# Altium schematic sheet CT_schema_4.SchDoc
size 396 x 205 mm
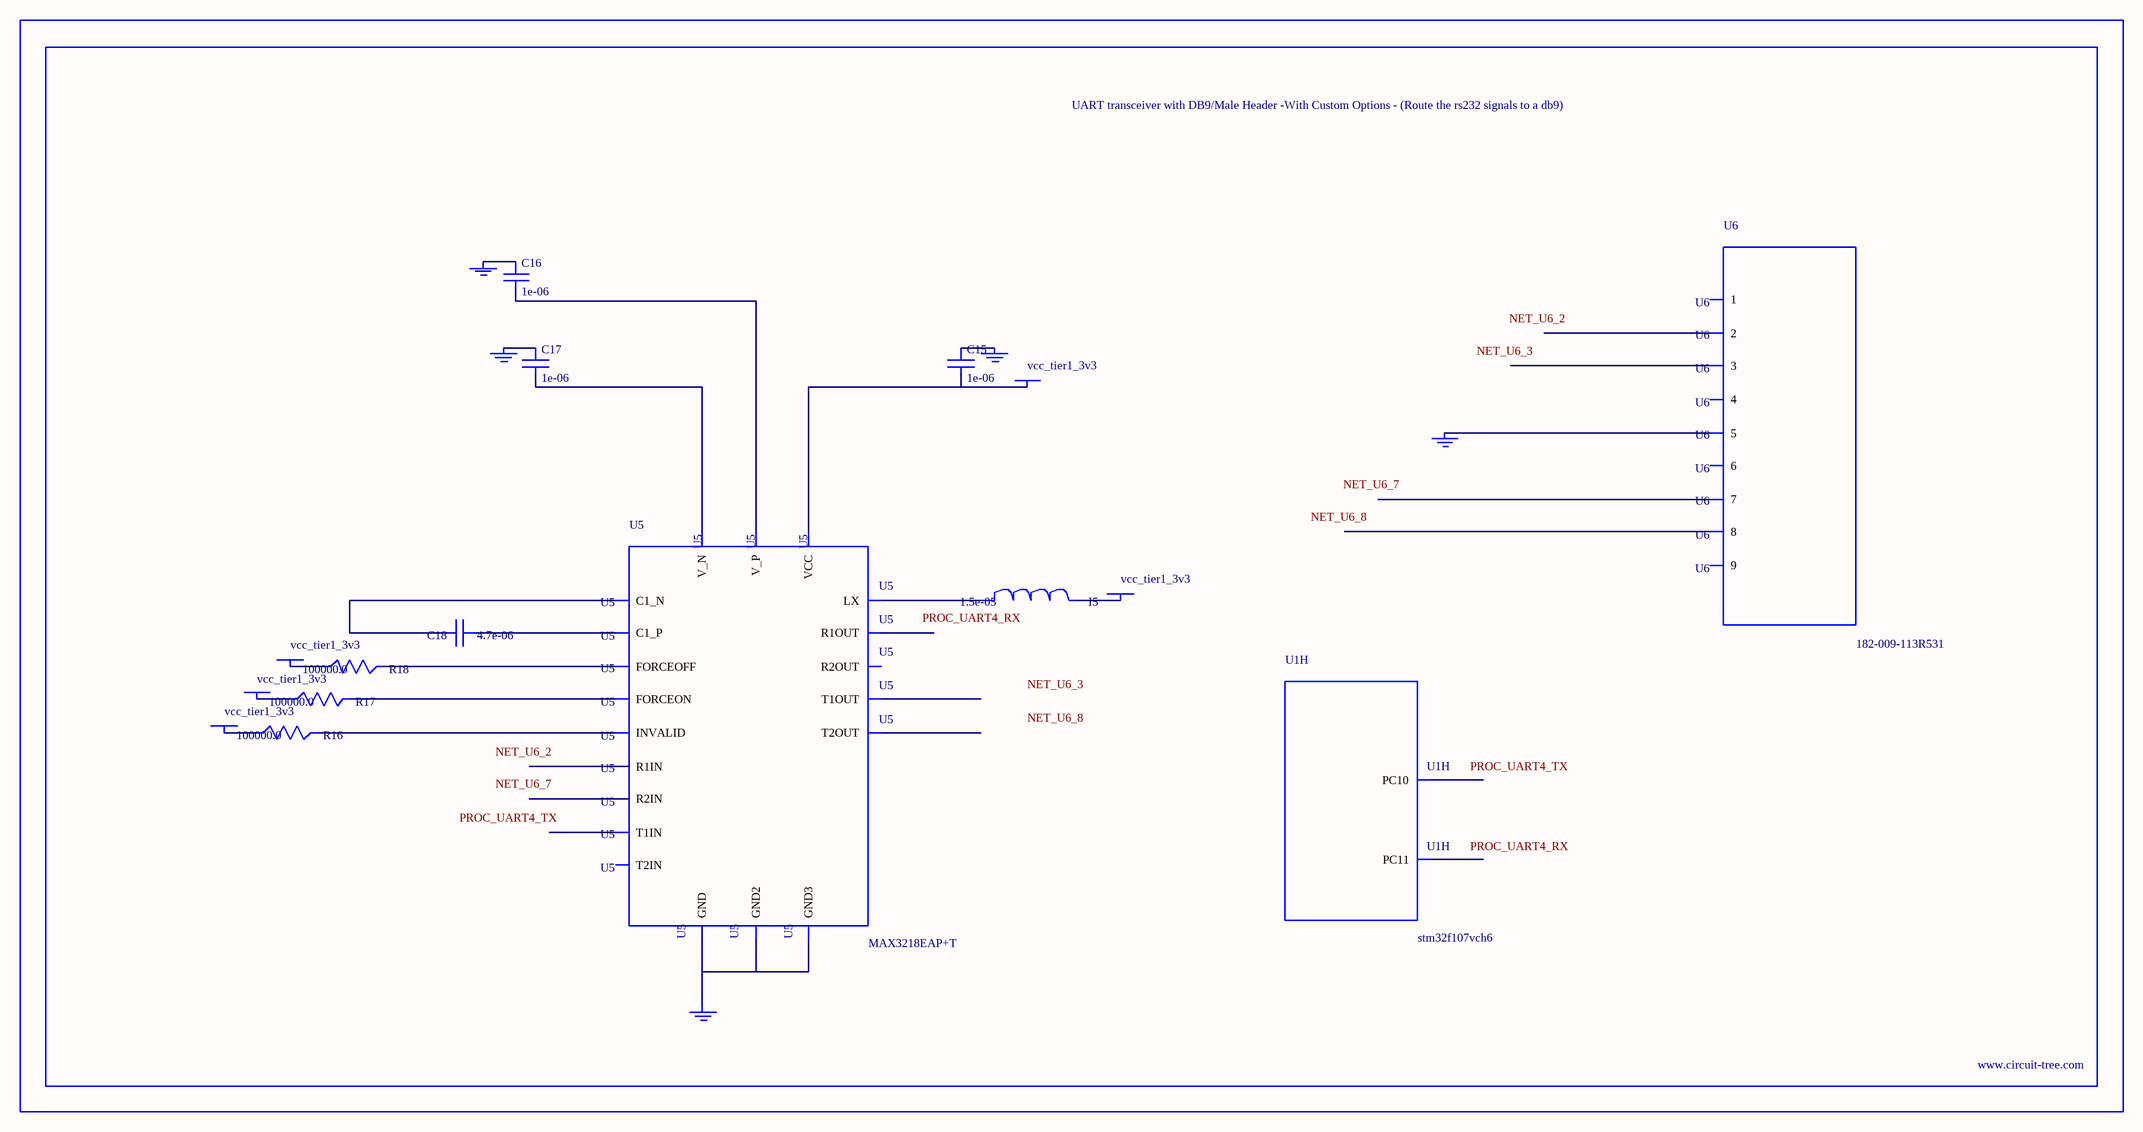
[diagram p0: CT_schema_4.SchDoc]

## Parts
BORDER3  (no value)
C15  1e-06  [C0603]
C16  1e-06  [C0603]
C17  1e-06  [C0603]
C18  4.7e-06  [C0805]
GND_INSTANCE_3_0  (no value)
GND_INSTANCE_3_1  (no value)
GND_INSTANCE_3_2  (no value)
GND_INSTANCE_3_3  (no value)
GND_INSTANCE_3_4  (no value)
I5  1.5e-05  [L1210]
POWER_INSTANCE_3_0  vcc_tier1_3v3
POWER_INSTANCE_3_1  vcc_tier1_3v3
POWER_INSTANCE_3_2  vcc_tier1_3v3
POWER_INSTANCE_3_3  vcc_tier1_3v3
POWER_INSTANCE_3_4  vcc_tier1_3v3
R16  100000.0  [R0603]
R17  100000.0  [R0603]
R18  100000.0  [R0603]
U1  stm32f107vch6  [LFBGA100]  (part H of 9)
U5  MAX3218EAP+T  [SSOP-20]
U6  182-009-113R531  [182-009-MALE]

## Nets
NetC15_1: C15.1 GND_INSTANCE_3_0.0(GND)
NetC15_2: C15.2 POWER_INSTANCE_3_4.0(PWR) U5.6(VCC)
NetC16_1: C16.1 GND_INSTANCE_3_2.0(GND)
NetC16_2: C16.2 U5.19(V_P)
NetC17_1: C17.1 GND_INSTANCE_3_1.0(GND)
NetC17_2: C17.2 U5.15(V_N)
NetC18_1: C18.1 U5.18(C1_P)
NetC18_2: C18.2 U5.16(C1_N)
NetGND_INSTANCE_3_3_0: GND_INSTANCE_3_3.0(GND) U5.5(GND) U5.17(GND2) U5.20(GND3)
NetGND_INSTANCE_3_4_0: GND_INSTANCE_3_4.0(GND) U6.5
NetI5_1: I5.1 U5.1(LX)
NetI5_2: I5.2 POWER_INSTANCE_3_0.0(PWR)
NetPOWER_INSTANCE_3_1_0: POWER_INSTANCE_3_1.0(PWR) R16.1
NetPOWER_INSTANCE_3_2_0: POWER_INSTANCE_3_2.0(PWR) R17.1
NetPOWER_INSTANCE_3_3_0: POWER_INSTANCE_3_3.0(PWR) R18.1
NetR16_2: R16.2 U5.2(INVALID)
NetR17_2: R17.2 U5.3(FORCEON)
NetR18_2: R18.2 U5.4(FORCEOFF)

Not connected (* = marked no-connect by the designer): U1 B8(PC11) B9(PC10); U5 7(T1IN) 8(T2IN) 9(R1OUT) 10(R2OUT) 11(R2IN) 12(R1IN) 13(T2OUT) 14(T1OUT); U6 1 2 3 4 6 7 8 9

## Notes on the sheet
- Labels drawn without touching a wire or pin: NET_U6_2, NET_U6_3, NET_U6_7, NET_U6_8, PROC_UART4_RX, PROC_UART4_TX

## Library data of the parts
BORDER3 = BORDER_PAGE3
C15-C17 = C0603C105K3RACTU
C18 = C0805C475K4RACTU
GND_INSTANCE_3_0-GND_INSTANCE_3_4 = GND
I5 = L1210R150MDWIT
POWER_INSTANCE_3_0-POWER_INSTANCE_3_4 = PWR
R16-R18 = RC0603JR-07100KL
